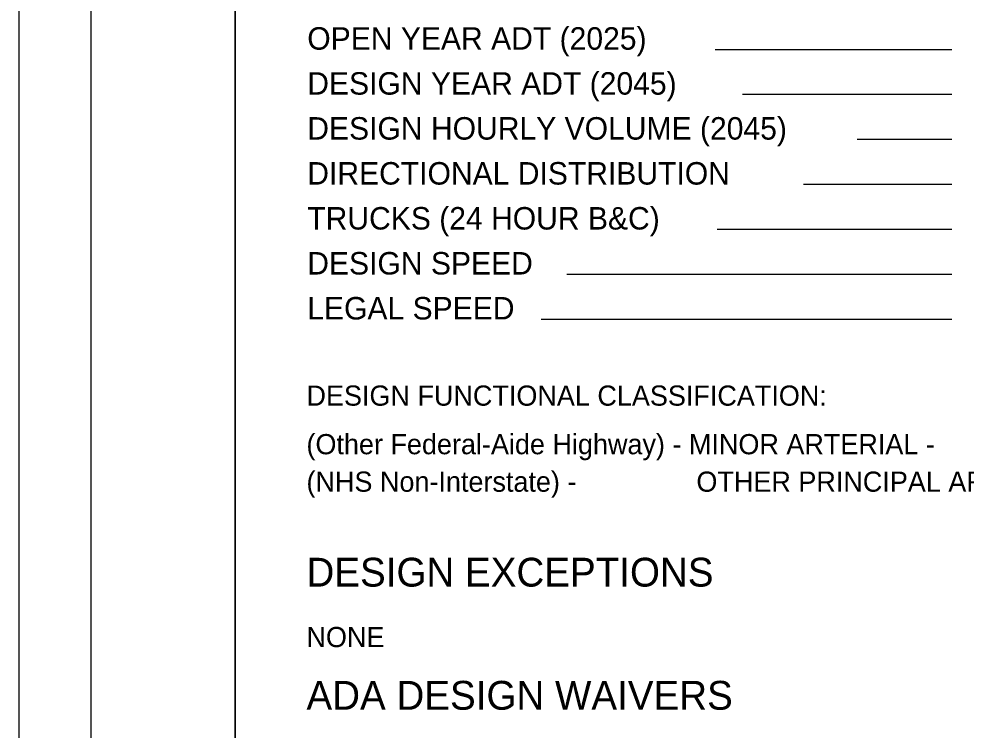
# Model space of a CAD drawing. Extents: x -10.1 to 68, y -9.5 to 29.2.
# Drawn here: x 0 to 6.57, y 4.93 to 9.87 of the extents above; entities that cross this region are included whole.
import ezdxf

# ---------------------------------------------------------------- set-up
doc = ezdxf.new("R2010")
doc.units = 0
for name, color, linetype in [('SH_Border', 7, 'Continuous'), ('SH_Cut_Line', 7, 'Continuous'), ('SH_Data', 7, 'Continuous'), ('SH_Text', 7, 'Continuous')]:
    doc.layers.add(name, color=color, linetype=linetype)

msp = doc.modelspace()

# ---------------------------------------------------------------- linework, layer by layer
at = {"layer": 'SH_Border'}
for points in [[(0.5, 21.5), (1.5, 21.5), (1.5, 0.5), (0.5, 0.5)], [(1.5, 21.5), (33.5, 21.5), (33.5, 0.5), (1.5, 0.5)]]:
    msp.add_lwpolyline(points, close=True, dxfattribs=at)
at = {"layer": 'SH_Cut_Line'}
msp.add_lwpolyline([(0, 0), (34, 0), (34, 22), (0, 22)], close=True, dxfattribs=at)
at = {"layer": 'SH_Data'}
for p, q in [((6.4707, 9.6556), (4.8302, 9.6556)), ((6.4707, 9.3436), (5.019, 9.3436)), ((6.4707, 9.0316), (5.8146, 9.0316)), ((6.4707, 8.7196), (5.4429, 8.7196)), ((6.4707, 8.4076), (4.8429, 8.4076)), ((6.4707, 8.0956), (3.7995, 8.0956)), ((6.4707, 7.7836), (3.6234, 7.7836))]:
    msp.add_line(p, q, dxfattribs=at)

# ---------------------------------------------------------------- texts
for s, height, p in [('OPEN YEAR ADT (2025)', 0.156, (2, 9.6556)), ('DESIGN YEAR ADT (2045)', 0.156, (2, 9.3436)), ('DESIGN HOURLY VOLUME (2045)', 0.156, (2, 9.0316)), ('DIRECTIONAL DISTRIBUTION', 0.155966, (2, 8.7196)), ('TRUCKS (24 HOUR B&C)', 0.155966, (2, 8.4076)), ('DESIGN SPEED', 0.155966, (2, 8.0955)), ('LEGAL SPEED', 0.155966, (2, 7.7835))]:
    msp.add_text(s, height=height, dxfattribs=at).set_placement(p)
at = {"layer": 'SH_Text'}
for s, height, p in [('DESIGN FUNCTIONAL CLASSIFICATION:', 0.14, (1.9944, 7.1853)), ('(Other Federal-Aide Highway) - MINOR ARTERIAL -                   (SLM 0.00 - 2.54) - ( STP Rural )', 0.14, (1.9944, 6.8483)), ('(NHS Non-Interstate) -                OTHER PRINCIPAL ARTERIAL - (SLM 2.54 - 2.81) - ( NHS Rural )', 0.14, (1.9944, 6.5882)), ('DESIGN EXCEPTIONS', 0.2, (1.9944, 5.9301)), ('NONE', 0.14, (1.9944, 5.5101)), ('ADA DESIGN WAIVERS', 0.2, (1.9944, 5.0756))]:
    msp.add_text(s, height=height, dxfattribs=at).set_placement(p)

doc.saveas('drawing.dxf')
